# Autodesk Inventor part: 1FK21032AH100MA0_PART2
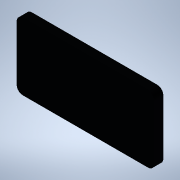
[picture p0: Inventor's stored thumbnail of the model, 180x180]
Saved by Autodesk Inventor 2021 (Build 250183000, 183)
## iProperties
Created: 2025-04
Part Number: 1FK21032AH100MA0_PART2
Material: Generic
Catalog Web Link: www.3dfindit.com
Description: -Servo synchronous motor
Document SubType Name: Modeling
Designer: psAdmin
Mass: 2.9597 g
Surface Area: 23.6483 cm^2
Volume: 2.9597 cm^3
Density: 1 g/cm^3
Appearance: PSOLRGB-38-46-56
Category: PARTsolutions
Title: 1FK21032AH100MA0_PART2
Author: Cadenas PARTsolutions
Comments: Servo synchronous motor
Sending System: PARTsolutions
Preprocessor: ST-DEVELOPER v19.3
PSOL_IDENT_0: {$CADENAS_DATA/23d-libs/siemens_ag/_cat_/12/33/1fk21032ah100ma0.prj},213 {VTYP=3D},{NB=1FK21032AH100
PSOL_IDENT_1: MA0_PART2},{LINA=1FK21032AH100MA0_PART2},{NN=1FK21032AH100MA0_PART2},{NOPRJ=TRUE},{DATE=19.08.2025 1
PSOL_IDENT_2: 4:00:27},{GEOMDATE=30.07.2025 02:02:58},{VERSION=},{LINEID=10},{WBVAR=},{WBNUMERIC=}  {NB=1FK21032AH
PSOL_IDENT_3: 100MA0_PART2},{LINA=1FK21032AH100MA0_PART2},{KT=DUMMY},{PREVIEW=../../../_pool_/d3/78/p_d211_xx_0093
PSOL_IDENT_4: 4j.png},{DESCSHORT=SIMOTICS S-1FK2 HD, SINAMICS S210 3AC 400V-480V, 0.59 Nm, 4500 rpm},{DESCLONG=SIM
PSOL_IDENT_5: OTICS S-1FK2 HD servo motor M0=0.64 Nm; PN = 0.28 kW at nN=4500 rpm (380-480 V); PN = 0.167 kW at nN=
PSOL_IDENT_6: 2500 rpm (200-240 V); with holding brake; degree of protection IP64; cylindrical shaft D14 x 30 mm;
PSOL_IDENT_7: absolute encoder 22-bit + 12-bit multiturn (encoder AM22DQC); with OCC interface; plug size M17, rot
PSOL_IDENT_8: atable; SIMOTICS S-1FK2 servomotorfor a wide range of uses in industrial environments. SIMOTICS S‑1F
PSOL_IDENT_9: K2 servomotors are compact synchronous motors with a high dynamic performance that set themselves ap
PSOL_IDENT_10: art as a result of their high power density, degree of protection and overload capability. The motor
PSOL_IDENT_11: s are available in two variants: as High Dynamic variant (highest dynamic performance as a result of
PSOL_IDENT_12: the low intrinsic moment of inertia for applications demanding a high dynamic performance with low
PSOL_IDENT_13: moved masses) - and as Compact variant (precise and stable closed-loop control for medium up to larg
PSOL_IDENT_14: e moved masses as a result of a medium intrinsic moment of inertia). SIMOTICSS‑1FK2 servomotors full
PSOL_IDENT_15: y exploit their strengths in a system with the SINAMICSS210 frequency converter and simple connectio
PSOL_IDENT_16: n using the one cable connection (OCC). Advantages include the short control and positioning times,
PSOL_IDENT_17: fast and precise correction of disturbing quantities as well as stable control with a high dynamic p
PSOL_IDENT_18: erformance. The servo motors can be configured to address a wide range of requirements. For example
PSOL_IDENT_19: with and without holding brake, IP64 or IP65 degree of protection, singleturn or multiturn absolute
PSOL_IDENT_20: encoders - to name just a few. Further, the servomotors are available in different shaft heights ext
PSOL_IDENT_21: ending from 20 to 100. A shaft sealing ring is available to achieve an IP65 degree of protection and
PSOL_IDENT_22: for subsequent mounting at the motor or as spare part. SIMOTICS - the optimum motor for each and ev
PSOL_IDENT_23: ery motion control application.},{INTNO=195125315563},{SUPPLIERALTNO=1FK2103-2AH10-0MA0},{MANUID=1FK
PSOL_IDENT_24: 21032AH100MA0},{MANUNAME=Siemens},{MANUTYPEDESC=SYNCHRONOUS MOTOR 1FK2 HD 0,64 NM},{AAU732=SIMOTICS}
PSOL_IDENT_25: ,{AAO057=S-1FK2},{AAU734=SIMOTICS S-1FK2 HD servo motor M0=0.64 Nm; PN = 0.28 kW at nN=4500 rpm (380
PSOL_IDENT_26: -480 V); PN = 0.167 kW at nN=2500 rpm (200-240 V); with holding brake; degree of protection IP64; cy
PSOL_IDENT_27: lindrical shaft D14 x 30 mm; absolute encoder 22-bit + 12-bit multiturn (encoder AM22DQC); with OCC
PSOL_IDENT_28: interface; plug size M17, rotatable;},{AAW338=SYNCHRONOUS MOTOR 1FK2 HD 0,64 NM},{AAO742=SIMOTICS},{
PSOL_IDENT_29: AAO663=4034106444723},{NOCUPEROU=1},{PRICEQUANTITY=1},{QUANTITYMIN=1},{QUANTITYINT=1},{CTN=85015100}
PSOL_IDENT_30: ,{COO=RO},{AAO676=1FK2103-2AH10-0MA0},{AAO677=Siemens AG},{ORDERUNIT=C62},{CONTENTUNIT=C62}
NB: 1FK21032AH100MA0_PART2
NT: Servo synchronous motor
NBSYN: $MANUID._PART2
LINA: 1FK21032AH100MA0_PART2
CATALOG: SIEMENS
PREVIEW: ../../../_pool_/d3/78/p_d211_xx_00934j.png
DESCSHORT: SIMOTICS S-1FK2 HD, SINAMICS S210 3AC 400V-480V, 0.59 Nm, 4500 rpm
DESCLONG: SIMOTICS S-1FK2 HD servo motor M0=0.64 Nm; PN = 0.28 kW at nN=4500 rpm (380-480 V); PN = 0.167 kW at nN=2500 rpm (200-240 V); with holding brake; degree of prot
INTNO: 195125315563
SUPPLIERALTNO: 1FK2103-2AH10-0MA0
MANUID: 1FK21032AH100MA0
MANUNAME: Siemens
MANUTYPEDESC: SYNCHRONOUS MOTOR 1FK2 HD 0,64 NM
AAU732: SIMOTICS
AAO057: S-1FK2
AAU734: SIMOTICS S-1FK2 HD servo motor M0=0.64 Nm; PN = 0.28 kW at nN=4500 rpm (380-480 V); PN = 0.167 kW at nN=2500 rpm (200-240 V); with holding brake; degree of prot
AAW338: SYNCHRONOUS MOTOR 1FK2 HD 0,64 NM
AAO742: SIMOTICS
AAO663: 4034106444723.0
NOCUPEROU: 1
PRICEQUANTITY: 1
QUANTITYMIN: 1
QUANTITYINT: 1
CTN: 85015100
COO: RO
ARTICLENO: 1FK21032AH100MA0_PART2
BOMINFO: 1FK21032AH100MA0_PART2
CREATOR: CADENAS GmbH
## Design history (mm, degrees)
feature "2025_04_17_15_06_16_0580"
body "Solid1"
